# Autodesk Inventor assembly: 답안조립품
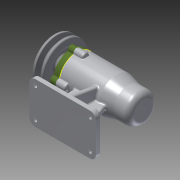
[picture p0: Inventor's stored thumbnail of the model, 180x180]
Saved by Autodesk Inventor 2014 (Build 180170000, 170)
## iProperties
Created: 2019-07
Part Number: 답안조립품
Document SubType Name: Assembly
Designer: net
Author: net
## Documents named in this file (12)
- C:\Users\net\Desktop\490704V1053\답안조립품.iam
- C:\Users\net\Desktop\490704V1053\답안본체.ipt
- C:\Users\net\Desktop\490704V1053\축.ipt
- C:\Users\net\Desktop\490704V1053\베어링 6004.ipt
- C:\Users\net\Desktop\490704V1053\어댑터슬리브.ipt
- C:\Users\net\Desktop\490704V1053\베어링 51202.ipt
- C:\Users\net\Desktop\490704V1053\볼트 M4.ipt
- C:\Users\net\Desktop\490704V1053\커버.ipt
- C:\Users\net\Desktop\490704V1053\오일 실.ipt
- C:\Users\net\Desktop\490704V1053\키 5 x 5 x 16.ipt
- C:\Users\net\Desktop\490704V1053\V벨트풀리.ipt
- C:\Users\net\Desktop\490704V1053\멈춤나사 M3.ipt
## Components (1 placed, 1 different names)
1. V벨트풀리:1
